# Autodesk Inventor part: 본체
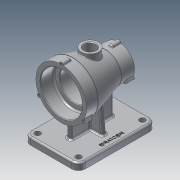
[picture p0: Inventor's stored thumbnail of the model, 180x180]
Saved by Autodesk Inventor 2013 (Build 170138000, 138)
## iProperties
Created: 2020-03
Part Number: 본체
Material: 알루미늄 6061
Document SubType Name: Modeling
Designer: user
Density: 2.71 g/cm^3
Mass: 989.89 g
Surface Area: 854.685 cm^2
Volume: 365.273 cm^3
Author: user
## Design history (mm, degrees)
sketch "스케치5"
  geometry: L1 (-50, 44)-(-30, 44); L2 (-30, 44)-(27, 27.5); L3 (27, 27.5)-(50, 27.5); L4 (50, 27.5)-(50, 0); L5 (50, 0)-(-50, 0); L6 (-50, 0)-(-50, 44); 2 further points
  constraints: 12 end point, 3 parallel, 1 coincident, 1 horizontal, 1 midpoint, 1 perpendicular
  dimensions: "d25" = 20 distance of L1.start L1.end; "d27" = 77 distance from line of L2.end L6; "d28" = 100 distance between parallel lines of L4 L6; "d29" = 88 diameter of L1 L5; "d30" = 55 diameter of L3 L5
revolve "회전2" sketch "스케치5" stored, may be unused: angle "d31" = 90 deg
sketch "스케치6"
  geometry: C1 r 44 at (0, 0) reference; C2 r 36 at (0, 0)
  constraints: 1 centre point, 1 coincident
  dimensions: "d32" = 72 diameter of C2
extrude "돌출4" cut sketch "스케치6" distance "d34" = 23; taper "d35" = 0 deg
sketch "스케치7"
  geometry: C1 r 36 at (0, 0) reference; C2 r 26 at (0, 0)
  constraints: 1 centre point, 1 coincident
  dimensions: "d36" = 52 diameter of C2
extrude "돌출5" cut sketch "스케치7" distance "d38" = 47; taper "d39" = 0 deg
sketch "스케치8"
  geometry: C1 r 26 at (0, 0) reference; C2 r 20 at (0, 0)
  constraints: 1 centre point, 1 coincident
  dimensions: "d40" = 40 diameter of C2
extrude "돌출6" cut sketch "스케치8" distance "d42" = 30; taper "d43" = 0 deg
node "작업 평면1"
sketch "스케치9"
  geometry: L1 (-67.5, 47.5)-(67.5, 47.5); L2 (67.5, 47.5)-(67.5, -47.5); L3 (67.5, -47.5)-(-67.5, -47.5); L4 (-67.5, -47.5)-(-67.5, 47.5); L5 (-67.5, 47.5)-(67.5, -47.5); L6 (67.5, 47.5)-(-67.5, -47.5); 1 further point
  constraints: 12 end point, 2 midpoint, 2 parallel, 1 horizontal, 1 perpendicular
  dimensions: "d45" = 135 distance of L2.end L3.end; "d47" = 95 distance of L1.end L2.end
extrude "돌출7" join sketch "스케치9" distance "d48" = 12; taper "d49" = 0 deg
sketch "스케치10"
  geometry: L1 (37, -4)-(-37, -4); L2 (-37, -4)-(-37, 4); L3 (-37, 4)-(37, 4); L4 (37, 4)-(37, -4); L5 (37, -4)-(-37, 4); L6 (-37, -4)-(37, 4); 1 further point
  constraints: 12 end point, 2 midpoint, 2 parallel, 1 horizontal, 1 perpendicular
  dimensions: "d50" = 74 distance of L2.end L3.end; "d52" = 8 distance of L1.end L2.end
extrude "돌출8" join sketch "스케치10" stored distance "d53" = 12; taper "d54" = 0 deg
sketch "스케치11"
  geometry: L1 (-87, 47.5)-(-75, 47.5) reference; L2 (-75, 47.5)-(-75, 4) reference; L3 (-75, 4)-(-35.089, 4) reference; L4 (-35.089, -4)-(-75, -4) reference; L5 (-75, -4)-(-75, -47.5) reference; L6 (-75, -47.5)-(-87, -47.5) reference; L7 (-87, -47.5)-(-87, 47.5) reference; L8 (-28.447, 20.927)-(-75, 25); C1 r 26 at (0, 0) reference; A1 r 35.316 centre (0, 0) between (-35.089, -4) and (-35.089, 4) reference; 1 further point
  constraints: 2 end point, 1 point on circle, 1 point on line
  dimensions: "d56" = 25 vertical distance of point (0, 0) L8.end; "d57" = 95 deg angle of L2 L8
feature "리브1" sketch "스케치11" dims "d58" = 1, "d59" = 8, "d60" = 0, "d61" = 0, "d62" = 1, "d63" = 1
node "작업 평면2"
sketch "스케치12"
  geometry: C1 r 15 at (0, 0); 1 further point
  constraints: 1 centre point, 1 coincident
  dimensions: "d65" = 30 diameter of C1
extrude "돌출9" join sketch "스케치12" stored distance "d67" = 12; taper "d68" = 0 deg
sketch "스케치13"
  geometry: 1 further point
sketch "스케치14"
  geometry: C1 r 15 at (0, 0) reference; C2 r 10 at (0, 0)
  constraints: 1 centre point, 1 coincident
  dimensions: "d69" = 20 diameter of C2
extrude "돌출10" cut sketch "스케치14" distance "d71" = 27.25; taper "d72" = 0 deg
sketch "스케치15"
  geometry: L1 (67.5, 47.5)-(-67.5, 47.5) reference; L2 (-67.5, 47.5)-(-67.5, -47.5) reference; 2 further points
  dimensions: "d73" = 12 distance from line of point (-55.5, 35.5) L1; "d74" = 12 distance from line of point (-55.5, 35.5) L2
hole "구멍1" sketch "스케치15" at (-55.5, 35.5) diameter "d75" = 10; stored, may be unused: countersink angle "d79" = 90 deg, drill point angle "d81" = 118 deg; dims "d76" = 6, "d77" = 4, "d78" = 2, "d80" = 8
fillet "모깎기1" dims "d82" = 12
fillet "모깎기2" dims "d83" = 3
fillet "모깎기3" dims "d84" = 3
fillet "모깎기4" dims "d85" = 3
fillet "모깎기5" dims "d86" = 3
fillet "모깎기6" dims "d87" = 3
sketch "스케치16"
  geometry: C1 r 3.5 at (0, 44); A1 r 44 centre (0, 0) between (0, 44) and (-6.553, -43.509) reference; A2 r 44 centre (0, 0) between (6.553, -43.509) and (-6.553, -43.509) reference; 1 further point
  constraints: 2 point on circle, 1 centre point, 1 coincident
  dimensions: "d88" = 7 diameter of C1
extrude "돌출11" join sketch "스케치16" distance "d90" = 15; taper "d91" = 0 deg
sketch "스케치17"
  geometry: C1 r 20 at (0, 0) reference; C2 r 3.5 at (0, 27.5); 1 further point
  constraints: 2 vertical alignment, 1 centre point, 1 other
  dimensions: "d95" = 7 diameter of C2
extrude "돌출12" join sketch "스케치17" distance "d97" = 15; taper "d98" = 0 deg
sketch "스케치18"
  geometry: A1 r 3.5 centre (38.105, -66) between (36.236, -68.959) and (39.733, -62.902) reference; A2 r 3.5 centre (0, 0) between (3.497, -0.139) and (-3.497, -0.139) reference; A3 r 3.5 centre (-38.105, -66) between (-39.733, -62.902) and (-36.236, -68.959) reference
hole "구멍2" sketch "스케치18" at (0, 0), (38.105, -66), (-38.105, -66) diameter "d102" = 4.134; stored, may be unused: countersink angle "d106" = 90 deg, drill point angle "d108" = 118 deg; dims "d103" = 9, "d104" = 4, "d105" = 2, "d107" = 11
sketch "스케치19"
  geometry: A1 r 3.5 centre (0, 0) between (3.493, -0.223) and (-3.493, -0.223) reference; A2 r 3.5 centre (-23.816, -41.25) between (-25.369, -38.114) and (-21.876, -44.164) reference; A3 r 3.5 centre (23.816, -41.25) between (21.876, -44.164) and (25.369, -38.114) reference
hole "구멍3" sketch "스케치19" at (0, 0), (23.816, -41.25), (-23.816, -41.25) diameter "d109" = 4.134; stored, may be unused: countersink angle "d113" = 90 deg, drill point angle "d115" = 118 deg; dims "d110" = 9, "d111" = 4, "d112" = 2, "d114" = 11
fillet "모깎기7" dims "d116" = 3
fillet "모깎기8" dims "d117" = 1
chamfer "모따기1" distance "d118" = 1; stored, may be unused: second distance "d119" = 2, angle "d120" = 45 deg
fillet "모깎기9" dims "d121" = 1
fillet "모깎기10" dims "d122" = 3
chamfer "모따기2" distance "d123" = 1; stored, may be unused: second distance "d124" = 2, angle "d125" = 45 deg
chamfer "모따기3" distance "d126" = 1; stored, may be unused: second distance "d127" = 2, angle "d128" = 45 deg
node "작업 평면3"
sketch "스케치20"
  geometry: L1 (-55.5, -47.5)-(55.5, -47.5) reference; L2 (67.5, -35.5)-(67.5, 35.5) reference; 2 further points
  constraints: 1 other
  dimensions: "d130" = 10 distance from line of L1 point (0, -37.5); "d131" = 67.5 distance from line of L2 point (0, -37.5)
feature "엠보싱1" sketch "스케치20" dims "d36" = 52, "d132" = 0.5, "d133" = 0
node "솔리드2"
mirror "대칭1"
mirror "대칭2"
mirror "대칭3"
pattern_circular "원형 패턴1" dims angle "d93" = 360 deg
pattern_circular "원형 패턴2" dims angle "d100" = 360 deg
node "절단 모서리 투영1"
other parameters: "d44" = -87, "d64" = 45, "d129" = 18.5
